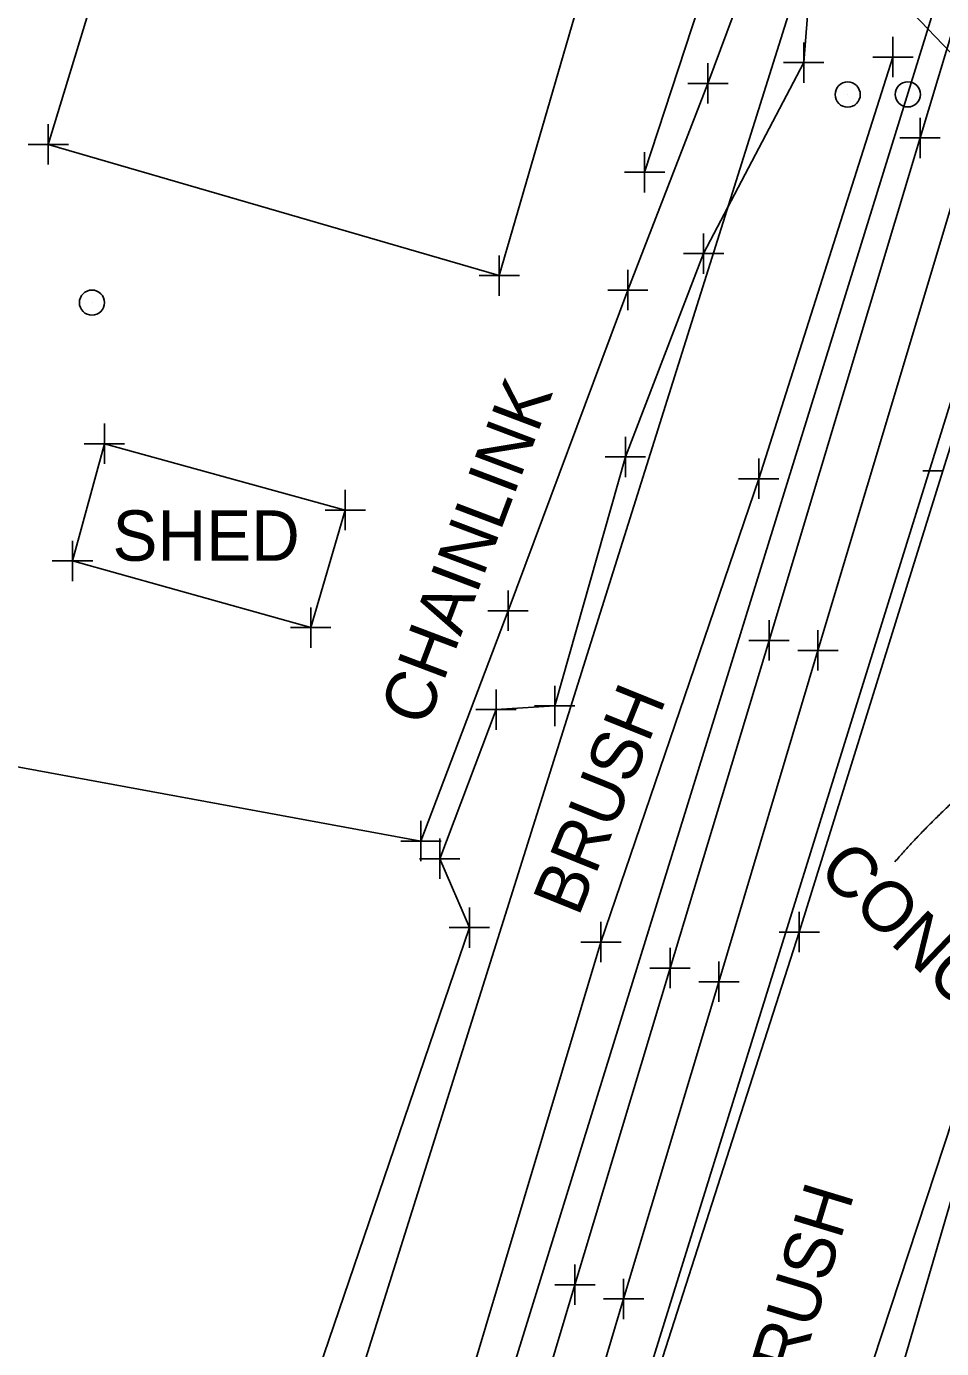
# Model space of a CAD drawing. Extents: x 0 to 1944463, y 0 to 420651.
# Drawn here: x 1943055.1 to 1943145.8, y 417335.4 to 417466.5 of the extents above; entities that cross this region are included whole.
import ezdxf

# ---------------------------------------------------------------- set-up
doc = ezdxf.new("R2010")
doc.units = 0
for name, color, linetype in [('SUR - DRG - Pipes and Culverts Text', 7, 'Continuous'), ('SUR - DTM - Breaklines', 7, 'Continuous'), ('SUR - DTM - Breaklines - Points - Locators', 7, 'Continuous'), ('SUR - DTM - Spot Points - Locators', 7, 'Continuous'), ('SUR - NON-TRAN - Buildings', 7, 'Continuous'), ('SUR - NON-TRAN - Buildings - Points - Locators', 7, 'Continuous'), ('SUR - NON-TRAN - Buildings Text', 7, 'Continuous'), ('SUR - NON-TRAN - Features', 7, 'Continuous'), ('SUR - NON-TRAN - Features - Points - Locators', 7, 'Continuous'), ('SUR - NON-TRAN - Features Text', 7, 'Continuous'), ('SUR - TRAN - Railroads', 7, 'Continuous'), ('SUR - TRAN - Railroads - Points - Locators', 7, 'Continuous'), ('SUR - UTL - Overhead Wire Crossings', 7, 'Continuous'), ('SUR - VEG - Features', 7, 'Continuous'), ('SUR - VEG - Features Text', 7, 'Continuous')]:
    doc.layers.add(name, color=color, linetype=linetype)

msp = doc.modelspace()

# ---------------------------------------------------------------- linework, layer by layer
at = {"layer": 'SUR - DRG - Pipes and Culverts Text'}
msp.add_open_spline([(1943141.21, 417383.63), (1943146.21, 417389.36), (1943157.86, 417398.3), (1943157.86, 417398.3)], degree=2, dxfattribs=at)
at = {"layer": 'SUR - DTM - Breaklines'}
for points in [[(1943125.26, 417480.44), (1943123.1, 417472.52), (1943116.38, 417452)], [(1943133.1, 417474.8), (1943132.17, 417462.89), (1943122.24, 417443.95), (1943114.48, 417423.78), (1943107.47, 417399.09), (1943101.65, 417398.72), (1943096.06, 417383.93), (1943099.01, 417377.11), (1943083.08, 417330.36), (1943071.96, 417297.01), (1943056.58, 417252.03)], [(1943072.65, 417242.91), (1943084.6, 417287.36), (1943098.67, 417331.06), (1943112.05, 417375.67), (1943127.71, 417421.62), (1943141.02, 417463.43)], [(1943088.85, 417235.62), (1943103.52, 417283.36), (1943116.73, 417330), (1943131.72, 417376.66), (1943145.98, 417422.39), (1943153.32, 417445.75)], [(1943114.51, 417234.88), (1943128.23, 417282.69), (1943140.85, 417329.77), (1943154.73, 417377.21), (1943160.7, 417388.38)]]:
    msp.add_lwpolyline(points, dxfattribs=at)
at = {"layer": 'SUR - DTM - Breaklines - Points - Locators'}
for p, q in [((1943132.17, 417462.89), (1943132.17, 417464.89)), ((1943141.02, 417463.43), (1943141.02, 417465.43)), ((1943141.02, 417463.43), (1943139.02, 417463.43)), ((1943141.02, 417463.43), (1943143.02, 417463.43)), ((1943141.02, 417463.43), (1943141.02, 417461.43)), ((1943132.17, 417462.89), (1943130.17, 417462.89)), ((1943132.17, 417462.89), (1943134.17, 417462.89)), ((1943132.17, 417462.89), (1943132.17, 417460.89)), ((1943116.38, 417452), (1943116.38, 417454)), ((1943116.38, 417452), (1943114.38, 417452)), ((1943116.38, 417452), (1943118.38, 417452)), ((1943116.38, 417452), (1943116.38, 417450)), ((1943122.24, 417443.95), (1943122.24, 417445.95)), ((1943122.24, 417443.95), (1943120.24, 417443.95)), ((1943122.24, 417443.95), (1943124.24, 417443.95)), ((1943122.24, 417443.95), (1943122.24, 417441.95)), ((1943114.48, 417423.78), (1943114.48, 417425.78)), ((1943114.48, 417423.78), (1943112.48, 417423.78)), ((1943114.48, 417423.78), (1943116.48, 417423.78)), ((1943114.48, 417423.78), (1943114.48, 417421.78)), ((1943127.71, 417421.62), (1943127.71, 417423.62)), ((1943127.71, 417421.62), (1943125.71, 417421.62)), ((1943127.71, 417421.62), (1943129.71, 417421.62)), ((1943127.71, 417421.62), (1943127.71, 417419.62)), ((1943145.98, 417422.39), (1943143.98, 417422.39)), ((1943101.65, 417398.72), (1943101.65, 417400.72)), ((1943107.47, 417399.09), (1943107.47, 417401.09)), ((1943107.47, 417399.09), (1943105.47, 417399.09)), ((1943107.47, 417399.09), (1943109.47, 417399.09)), ((1943107.47, 417399.09), (1943107.47, 417397.09)), ((1943101.65, 417398.72), (1943099.65, 417398.72)), ((1943101.65, 417398.72), (1943103.65, 417398.72)), ((1943101.65, 417398.72), (1943101.65, 417396.72)), ((1943096.06, 417383.93), (1943096.06, 417385.93)), ((1943096.06, 417383.93), (1943094.06, 417383.93)), ((1943096.06, 417383.93), (1943098.06, 417383.93)), ((1943096.06, 417383.93), (1943096.06, 417381.93)), ((1943099.01, 417377.11), (1943099.01, 417379.11)), ((1943131.72, 417376.66), (1943131.72, 417378.66)), ((1943099.01, 417377.11), (1943097.01, 417377.11)), ((1943099.01, 417377.11), (1943101.01, 417377.11)), ((1943099.01, 417377.11), (1943099.01, 417375.11)), ((1943112.05, 417375.67), (1943112.05, 417377.67)), ((1943112.05, 417375.67), (1943110.05, 417375.67)), ((1943112.05, 417375.67), (1943114.05, 417375.67)), ((1943112.05, 417375.67), (1943112.05, 417373.67)), ((1943131.72, 417376.66), (1943129.72, 417376.66)), ((1943131.72, 417376.66), (1943133.72, 417376.66)), ((1943131.72, 417376.66), (1943131.72, 417374.66))]:
    msp.add_line(p, q, dxfattribs=at)
at = {"layer": 'SUR - DTM - Spot Points - Locators'}
for p, q in [((1943136.54, 417459.7), (1943136.54, 417459.7)), ((1943142.51, 417459.72), (1943142.51, 417459.72)), ((1943061.57, 417439.07), (1943061.57, 417439.07))]:
    msp.add_line(p, q, dxfattribs=at)
for centre in [(1943136.53, 417459.71), (1943142.5, 417459.73), (1943061.56, 417439.08)]:
    msp.add_circle(centre, 1.25, dxfattribs=at)
at = {"layer": 'SUR - NON-TRAN - Buildings'}
for points in [[(1943070.86, 417499.51), (1943057.23, 417454.76), (1943101.97, 417441.76), (1943115.02, 417486.68)], [(1943059.64, 417413.47), (1943083.27, 417406.85), (1943086.69, 417418.5), (1943062.79, 417425.09), (1943059.63, 417413.47)]]:
    msp.add_lwpolyline(points, close=True, dxfattribs=at)
at = {"layer": 'SUR - NON-TRAN - Buildings - Points - Locators'}
for p, q in [((1943057.23, 417454.76), (1943057.23, 417456.76)), ((1943057.23, 417454.76), (1943055.23, 417454.76)), ((1943057.23, 417454.76), (1943059.23, 417454.76)), ((1943057.23, 417454.76), (1943057.23, 417452.76)), ((1943101.97, 417441.76), (1943101.97, 417443.76)), ((1943101.97, 417441.76), (1943099.97, 417441.76)), ((1943101.97, 417441.76), (1943103.97, 417441.76)), ((1943101.97, 417441.76), (1943101.97, 417439.76)), ((1943062.79, 417425.09), (1943062.79, 417427.09)), ((1943062.79, 417425.09), (1943060.79, 417425.09)), ((1943062.79, 417425.09), (1943064.79, 417425.09)), ((1943062.79, 417425.09), (1943062.79, 417423.09)), ((1943086.69, 417418.5), (1943086.69, 417420.5)), ((1943086.69, 417418.5), (1943084.69, 417418.5)), ((1943086.69, 417418.5), (1943088.69, 417418.5)), ((1943086.69, 417418.5), (1943086.69, 417416.5)), ((1943059.63, 417413.47), (1943059.63, 417415.47)), ((1943059.64, 417413.47), (1943059.64, 417415.47)), ((1943059.64, 417413.47), (1943057.64, 417413.47)), ((1943059.64, 417413.47), (1943061.64, 417413.47)), ((1943059.64, 417413.47), (1943059.64, 417411.47)), ((1943059.63, 417413.47), (1943057.63, 417413.47)), ((1943059.63, 417413.47), (1943061.63, 417413.47)), ((1943059.63, 417413.47), (1943059.63, 417411.47)), ((1943083.27, 417406.85), (1943083.27, 417408.85)), ((1943083.27, 417406.85), (1943081.27, 417406.85)), ((1943083.27, 417406.85), (1943085.27, 417406.85)), ((1943083.27, 417406.85), (1943083.27, 417404.85))]:
    msp.add_line(p, q, dxfattribs=at)
at = {"layer": 'SUR - NON-TRAN - Buildings Text'}
msp.add_open_spline([(1943031.25, 417465.57), (1943038.96, 417462.82), (1943044.47, 417478.8), (1943071.28, 417471.27)], degree=2, dxfattribs=at)
at = {"layer": 'SUR - NON-TRAN - Features'}
msp.add_lwpolyline([(1943086.22, 417519.55), (1943090.06, 417525.73), (1943112.7, 417503.78), (1943130.81, 417482.77), (1943122.66, 417460.81), (1943114.72, 417440.32), (1943102.84, 417408.53), (1943094.19, 417385.68), (1943046.03, 417394.52), (1942997.48, 417404.12), (1942958.25, 417411.54), (1942930.05, 417417.01), (1942928.53, 417419.97)], dxfattribs=at)
at = {"layer": 'SUR - NON-TRAN - Features - Points - Locators'}
for p, q in [((1943122.66, 417460.81), (1943122.66, 417462.81)), ((1943122.66, 417460.81), (1943120.66, 417460.81)), ((1943122.66, 417460.81), (1943124.66, 417460.81)), ((1943122.66, 417460.81), (1943122.66, 417458.81)), ((1943114.72, 417440.32), (1943114.72, 417442.32)), ((1943114.72, 417440.32), (1943112.72, 417440.32)), ((1943114.72, 417440.32), (1943116.72, 417440.32)), ((1943114.72, 417440.32), (1943114.72, 417438.32)), ((1943102.84, 417408.53), (1943102.84, 417410.53)), ((1943102.84, 417408.53), (1943100.84, 417408.53)), ((1943102.84, 417408.53), (1943104.84, 417408.53)), ((1943102.84, 417408.53), (1943102.84, 417406.53)), ((1943094.19, 417385.68), (1943094.19, 417387.68)), ((1943094.19, 417385.68), (1943092.19, 417385.68)), ((1943094.19, 417385.68), (1943096.19, 417385.68)), ((1943094.19, 417385.68), (1943094.19, 417383.68))]:
    msp.add_line(p, q, dxfattribs=at)
at = {"layer": 'SUR - TRAN - Railroads'}
for points in [[(1943093.8, 417289.09), (1943099.68, 417308.96), (1943109.47, 417341.69), (1943118.91, 417373.09), (1943128.73, 417405.59), (1943143.71, 417455.42), (1943175.9, 417562.25), (1943188.11, 417602.58), (1943216.37, 417696.61), (1943236.5, 417763.05)], [(1943098.53, 417287.57), (1943104.56, 417307.63), (1943114.3, 417340.28), (1943123.75, 417371.73), (1943133.57, 417404.59), (1943148.36, 417453.81), (1943180.54, 417560.57), (1943192.93, 417601.39), (1943221.1, 417695.23), (1943241.09, 417761.6)]]:
    msp.add_lwpolyline(points, dxfattribs=at)
at = {"layer": 'SUR - TRAN - Railroads - Points - Locators'}
for p, q in [((1943143.71, 417455.42), (1943143.71, 417457.42)), ((1943143.71, 417455.42), (1943141.71, 417455.42)), ((1943143.71, 417455.42), (1943145.71, 417455.42)), ((1943143.71, 417455.42), (1943143.71, 417453.42)), ((1943128.73, 417405.59), (1943128.73, 417407.59)), ((1943133.57, 417404.59), (1943133.57, 417406.59)), ((1943128.73, 417405.59), (1943126.73, 417405.59)), ((1943128.73, 417405.59), (1943130.73, 417405.59)), ((1943128.73, 417405.59), (1943128.73, 417403.59)), ((1943133.57, 417404.59), (1943131.57, 417404.59)), ((1943133.57, 417404.59), (1943135.57, 417404.59)), ((1943133.57, 417404.59), (1943133.57, 417402.59)), ((1943118.91, 417373.09), (1943118.91, 417375.09)), ((1943118.91, 417373.09), (1943116.91, 417373.09)), ((1943118.91, 417373.09), (1943120.91, 417373.09)), ((1943118.91, 417373.09), (1943118.91, 417371.09)), ((1943123.75, 417371.73), (1943123.75, 417373.73)), ((1943123.75, 417371.73), (1943121.75, 417371.73)), ((1943123.75, 417371.73), (1943125.75, 417371.73)), ((1943123.75, 417371.73), (1943123.75, 417369.73)), ((1943109.47, 417341.69), (1943109.47, 417343.69)), ((1943109.47, 417341.69), (1943107.47, 417341.69)), ((1943109.47, 417341.69), (1943111.47, 417341.69)), ((1943109.47, 417341.69), (1943109.47, 417339.69)), ((1943114.3, 417340.28), (1943114.3, 417342.28)), ((1943114.3, 417340.28), (1943112.3, 417340.28)), ((1943114.3, 417340.28), (1943116.3, 417340.28)), ((1943114.3, 417340.28), (1943114.3, 417338.28))]:
    msp.add_line(p, q, dxfattribs=at)
at = {"layer": 'SUR - UTL - Overhead Wire Crossings'}
msp.add_lwpolyline([(1943056.4, 417558.26), (1943199.99, 417408.26)], dxfattribs=at)
at = {"layer": 'SUR - VEG - Features'}
msp.add_line((1943145.15, 417468.33), (1943084.66, 417273.14), dxfattribs=at)
for points in [[(1943071.54, 417279.76), (1943134.33, 417479.35), (1943145.15, 417468.33)], [(1943097.09, 417269.67), (1943155.49, 417457.32), (1943210.45, 417389.88), (1943185.65, 417378.15), (1943164.57, 417411.67), (1943116.14, 417264.55)]]:
    msp.add_lwpolyline(points, dxfattribs=at)

# ---------------------------------------------------------------- texts
at = {"layer": 'SUR - DRG - Pipes and Culverts Text'}
msp.add_text('CONC. DITCH', height=5, rotation=316.1519, dxfattribs=at).set_placement((1943133.4, 417382.53))
at = {"layer": 'SUR - NON-TRAN - Buildings Text'}
msp.add_text('SHED', height=5, dxfattribs=at).set_placement((1943063.6, 417413.48))
at = {"layer": 'SUR - NON-TRAN - Features Text'}
msp.add_text('CHAINLINK', height=5, rotation=69.281, dxfattribs=at).set_placement((1943094.71, 417396.86))
at = {"layer": 'SUR - VEG - Features Text'}
for rotation, p in [(68.0372, (1943109.82, 417378.09)), (73.1233, (1943130.42, 417328.29))]:
    msp.add_text('BRUSH', height=5, rotation=rotation, dxfattribs=at).set_placement(p)

doc.saveas('drawing.dxf')
